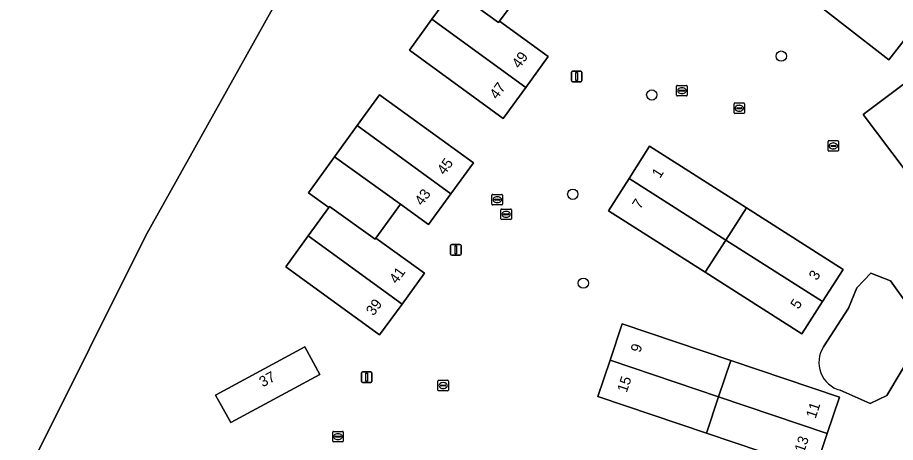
# Model space of a CAD drawing. Extents: x 159451 to 160664, y 388402 to 389723.
# Drawn here: x 159502.7 to 159586.1, y 389338.3 to 389378.7 of the extents above; entities that cross this region are included whole.
import ezdxf

# ---------------------------------------------------------------- set-up
doc = ezdxf.new("R2010")
doc.units = 0
for name, color, linetype in [('IMGEO_Boom', 7, 'Continuous'), ('IMGEO_Brandkraan', 7, 'Continuous'), ('IMGEO_Groenvoorziening', 7, 'Continuous'), ('IMGEO_Kolk', 7, 'Continuous'), ('IMGEO_Lichtmast', 7, 'Continuous'), ('IMGEO_Loofbos', 7, 'Continuous'), ('IMGEO_Meer_plas_ven_vijver', 7, 'Continuous'), ('IMGEO_Pand', 7, 'Continuous'), ('IMGEO_Pand_nummerreeks', 7, 'Continuous'), ('IMGEO_Rioolput', 7, 'Continuous')]:
    doc.layers.add(name, color=color, linetype=linetype)

msp = doc.modelspace()

# ---------------------------------------------------------------- linework, layer by layer
at = {"layer": 'IMGEO_Boom'}
for centre in [(159575.267, 389374.993), (159562.961, 389371.299), (159555.454, 389361.859), (159556.455, 389353.409)]:
    msp.add_circle(centre, 0.489, dxfattribs=at)
at = {"layer": 'IMGEO_Brandkraan'}
for p, q in [((159570.773, 389369.615), (159570.773, 389370.467)), ((159570.848, 389370.541), (159571.7, 389370.541)), ((159571.774, 389370.467), (159571.774, 389369.615)), ((159571.7, 389369.541), (159570.848, 389369.541)), ((159571.032, 389370.035), (159571.032, 389370.047)), ((159571.47, 389369.998), (159571.072, 389369.998)), ((159571.075, 389370.084), (159571.473, 389370.084)), ((159571.284, 389369.761), (159571.259, 389369.761)), ((159571.261, 389370.321), (159571.286, 389370.321)), ((159571.516, 389370.047), (159571.516, 389370.035))]:
    msp.add_line(p, q, dxfattribs=at)
for points in [[(159570.773, 389369.615), (159570.773, 389370.467)], [(159570.848, 389370.541), (159571.7, 389370.541)], [(159571.774, 389370.467), (159571.774, 389369.615)], [(159571.7, 389369.541), (159570.848, 389369.541)]]:
    msp.add_lwpolyline(points, dxfattribs=at)
for centre, radius, start, end in [((159570.85, 389370.465), 0.0765, 91.55205, 178.44795), ((159570.85, 389370.465), 0.0765, 91.55205, 178.44795), ((159571.698, 389370.465), 0.0765, 1.55205, 88.44795), ((159571.698, 389370.465), 0.0765, 1.55205, 88.44795), ((159570.85, 389369.617), 0.0765, 181.55205, 268.44795), ((159570.85, 389369.617), 0.0765, 181.55205, 268.44795), ((159571.072, 389370.044), 0.0403, 85.87752, 175.75265), ((159571.069, 389370.034), 0.0366, 178.93798, 274.71019), ((159571.473, 389370.041), 0.043, 264.86636, 352.45326), ((159571.477, 389370.046), 0.0386, 1.73085, 96.63898), ((159571.698, 389369.617), 0.0765, 271.55205, 358.44795), ((159571.698, 389369.617), 0.0765, 271.55205, 358.44795)]:
    msp.add_arc(centre, radius, start, end, dxfattribs=at)
for centre, major_axis, ratio, start_param, end_param in [((159571.26, 389370.041), (-0.387, 0.002), 0.722429, 4.712389, 7.853982), ((159571.285, 389370.041), (-0.39, 0.002), 0.717154, 1.570796, 4.712389)]:
    msp.add_ellipse(centre, major_axis=major_axis, ratio=ratio, start_param=start_param, end_param=end_param, dxfattribs=at)
at = {"layer": 'IMGEO_Groenvoorziening'}
for points in [[(159544.814, 389411.565), (159514.866, 389357.937), (159504.183, 389336.444), (159491.991, 389308.123), (159485.81, 389295.214), (159492.759, 389296.199), (159521.777, 389300.297)], [(159579.281, 389347.357), (159581.666, 389351.038), (159582.45, 389352.959), (159583.776, 389354.373), (159585.651, 389353.634), (159589.012, 389348.926)], [(159589.012, 389348.926), (159585.291, 389342.745), (159583.718, 389341.973), (159580.859, 389343.226)]]:
    msp.add_lwpolyline(points, dxfattribs=at)
for points in [[(159585.487, 389374.644), (159576.692, 389381.52), (159598.547, 389409.538), (159607.34, 389402.676)], [(159548.499, 389378.301), (159553.125, 389374.956), (159550.988, 389372.017), (159548.85, 389369.078), (159539.931, 389375.559), (159542.07, 389378.502), (159544.025, 389381.192), (159542.084, 389382.602), (159544.578, 389386.033), (159546.734, 389389), (159548.865, 389391.933), (159557.798, 389385.399), (159555.657, 389382.472), (159553.515, 389379.545), (159550.822, 389381.5)], [(159589.76, 389360.534), (159583.054, 389369.444), (159605.812, 389386.575), (159612.526, 389377.663)], [(159537.096, 389348.482), (159528.176, 389354.954), (159530.316, 389357.903), (159532.266, 389360.591), (159530.328, 389361.998), (159532.812, 389365.422), (159534.968, 389368.393), (159537.093, 389371.322), (159546.012, 389364.851), (159543.877, 389361.915), (159541.741, 389358.978), (159539.068, 389360.907), (159536.75, 389357.697), (159541.37, 389354.362), (159539.233, 389351.422)], [(159577.226, 389348.589), (159568.038, 389354.442), (159558.855, 389360.293), (159560.807, 389363.367), (159562.752, 389366.429), (159571.944, 389360.576), (159581.136, 389354.724), (159579.181, 389351.657)], [(159578.47, 389335.651), (159568.144, 389339.143), (159557.83, 389342.632), (159558.992, 389346.082), (159560.158, 389349.546), (159570.482, 389346.054), (159580.805, 389342.563), (159579.637, 389339.107)], [(159531.423, 389344.725), (159522.948, 389340.15), (159521.508, 389342.76), (159530.004, 389347.358)]]:
    msp.add_lwpolyline(points, close=True, dxfattribs=at)
msp.add_arc((159581.582, 389345.869), 2.74, 147.10719, 254.70551, dxfattribs=at)
at = {"layer": 'IMGEO_Kolk'}
for p, q in [((159565.323, 389371.283), (159565.323, 389372.135)), ((159565.398, 389372.209), (159566.25, 389372.209)), ((159566.324, 389372.135), (159566.324, 389371.283)), ((159566.25, 389371.209), (159565.398, 389371.209)), ((159565.582, 389371.703), (159565.582, 389371.715)), ((159566.02, 389371.666), (159565.622, 389371.666)), ((159565.625, 389371.752), (159566.023, 389371.752)), ((159565.834, 389371.429), (159565.809, 389371.429)), ((159565.811, 389371.989), (159565.836, 389371.989)), ((159566.066, 389371.715), (159566.066, 389371.703)), ((159542.632, 389343.252), (159542.632, 389344.104)), ((159542.707, 389344.178), (159543.559, 389344.178)), ((159542.891, 389343.672), (159542.891, 389343.684)), ((159542.934, 389343.721), (159543.332, 389343.721)), ((159543.12, 389343.958), (159543.145, 389343.958)), ((159543.375, 389343.684), (159543.375, 389343.672)), ((159543.633, 389344.104), (159543.633, 389343.252)), ((159543.559, 389343.178), (159542.707, 389343.178)), ((159543.329, 389343.635), (159542.931, 389343.635)), ((159543.143, 389343.398), (159543.118, 389343.398))]:
    msp.add_line(p, q, dxfattribs=at)
for points in [[(159565.323, 389371.283), (159565.323, 389372.135)], [(159565.398, 389372.209), (159566.25, 389372.209)], [(159566.324, 389372.135), (159566.324, 389371.283)], [(159566.25, 389371.209), (159565.398, 389371.209)], [(159542.632, 389343.252), (159542.632, 389344.104)], [(159542.707, 389344.178), (159543.559, 389344.178)], [(159543.633, 389344.104), (159543.633, 389343.252)], [(159543.559, 389343.178), (159542.707, 389343.178)]]:
    msp.add_lwpolyline(points, dxfattribs=at)
for centre, radius, start, end in [((159565.4, 389372.133), 0.0765, 91.55205, 178.44795), ((159565.4, 389372.133), 0.0765, 91.55205, 178.44795), ((159566.248, 389372.133), 0.0765, 1.55205, 88.44795), ((159566.248, 389372.133), 0.0765, 1.55205, 88.44795), ((159565.4, 389371.285), 0.0765, 181.55205, 268.44795), ((159565.4, 389371.285), 0.0765, 181.55205, 268.44795), ((159565.622, 389371.712), 0.0403, 85.87752, 175.75265), ((159565.619, 389371.702), 0.0366, 178.93798, 274.71019), ((159566.023, 389371.709), 0.043, 264.86636, 352.45326), ((159566.027, 389371.714), 0.0386, 1.73085, 96.63898), ((159566.248, 389371.285), 0.0765, 271.55205, 358.44795), ((159566.248, 389371.285), 0.0765, 271.55205, 358.44795), ((159542.709, 389344.102), 0.0765, 91.55205, 178.44795), ((159542.709, 389344.102), 0.0765, 91.55205, 178.44795), ((159542.931, 389343.681), 0.0403, 85.87752, 175.75265), ((159542.928, 389343.671), 0.0366, 178.93798, 274.71019), ((159543.332, 389343.678), 0.043, 264.86636, 352.45326), ((159543.336, 389343.683), 0.0386, 1.73085, 96.63898), ((159543.557, 389344.102), 0.0765, 1.55205, 88.44795), ((159543.557, 389344.102), 0.0765, 1.55205, 88.44795), ((159542.709, 389343.254), 0.0765, 181.55205, 268.44795), ((159542.709, 389343.254), 0.0765, 181.55205, 268.44795), ((159543.557, 389343.254), 0.0765, 271.55205, 358.44795), ((159543.557, 389343.254), 0.0765, 271.55205, 358.44795)]:
    msp.add_arc(centre, radius, start, end, dxfattribs=at)
for centre, major_axis, ratio, start_param, end_param in [((159565.81, 389371.709), (-0.387, 0.002), 0.722429, 4.712389, 7.853982), ((159565.835, 389371.709), (-0.39, 0.002), 0.717154, 1.570796, 4.712389), ((159543.119, 389343.678), (-0.387, 0.002), 0.722429, 4.712389, 7.853982), ((159543.144, 389343.678), (-0.39, 0.002), 0.717154, 1.570796, 4.712389)]:
    msp.add_ellipse(centre, major_axis=major_axis, ratio=ratio, start_param=start_param, end_param=end_param, dxfattribs=at)
at = {"layer": 'IMGEO_Lichtmast'}
for p, q in [((159555.326, 389372.663), (159555.326, 389373.463)), ((159555.326, 389373.463), (159555.326, 389372.663)), ((159555.426, 389373.563), (159556.216, 389373.563)), ((159556.216, 389373.563), (159555.426, 389373.563)), ((159556.316, 389373.463), (159556.316, 389372.663)), ((159556.316, 389372.663), (159556.316, 389373.463)), ((159556.216, 389372.563), (159555.426, 389372.563)), ((159555.426, 389372.563), (159556.216, 389372.563)), ((159543.945, 389357.081), (159544.735, 389357.081)), ((159544.735, 389357.081), (159543.945, 389357.081)), ((159543.845, 389356.181), (159543.845, 389356.981)), ((159543.845, 389356.981), (159543.845, 389356.181)), ((159544.835, 389356.981), (159544.835, 389356.181)), ((159544.835, 389356.181), (159544.835, 389356.981)), ((159544.735, 389356.081), (159543.945, 389356.081)), ((159543.945, 389356.081), (159544.735, 389356.081)), ((159535.364, 389344.07), (159535.364, 389344.87)), ((159535.364, 389344.87), (159535.364, 389344.07)), ((159535.464, 389344.97), (159536.254, 389344.97)), ((159536.254, 389344.97), (159535.464, 389344.97)), ((159536.354, 389344.87), (159536.354, 389344.07)), ((159536.354, 389344.07), (159536.354, 389344.87)), ((159536.254, 389343.97), (159535.464, 389343.97)), ((159535.464, 389343.97), (159536.254, 389343.97))]:
    msp.add_line(p, q, dxfattribs=at)
for points in [[(159555.746, 389373.438), (159555.896, 389373.438), (159555.896, 389372.688), (159555.746, 389372.688), (159555.746, 389373.438)], [(159544.265, 389356.956), (159544.415, 389356.956), (159544.415, 389356.206), (159544.265, 389356.206), (159544.265, 389356.956)], [(159535.784, 389344.845), (159535.934, 389344.845), (159535.934, 389344.095), (159535.784, 389344.095), (159535.784, 389344.845)]]:
    msp.add_lwpolyline(points, dxfattribs=at)
for centre, start, end in [((159555.426, 389373.463), 90, 180), ((159555.426, 389373.463), 90, 180), ((159556.216, 389373.463), 0, 90), ((159556.216, 389373.463), 360, 90), ((159555.426, 389372.663), 180, 270), ((159555.426, 389372.663), 180, 270), ((159556.216, 389372.663), 270, 0), ((159556.216, 389372.663), 270, 0), ((159543.945, 389356.981), 90, 180), ((159543.945, 389356.981), 90, 180), ((159544.735, 389356.981), 0, 90), ((159544.735, 389356.981), 360, 90), ((159543.945, 389356.181), 180, 270), ((159543.945, 389356.181), 180, 270), ((159544.735, 389356.181), 270, 0), ((159544.735, 389356.181), 270, 0), ((159535.464, 389344.87), 90, 180), ((159535.464, 389344.87), 90, 180), ((159536.254, 389344.87), 0, 90), ((159536.254, 389344.87), 360, 90), ((159535.464, 389344.07), 180, 270), ((159535.464, 389344.07), 180, 270), ((159536.254, 389344.07), 270, 0), ((159536.254, 389344.07), 270, 0)]:
    msp.add_arc(centre, 0.1, start, end, dxfattribs=at)
at = {"layer": 'IMGEO_Loofbos'}
msp.add_lwpolyline([(159475.093, 389317.376), (159476.799, 389293.936), (159485.81, 389295.214), (159491.991, 389308.123), (159504.183, 389336.444), (159514.866, 389357.937), (159544.814, 389411.565)], dxfattribs=at)
at = {"layer": 'IMGEO_Meer_plas_ven_vijver'}
for points in [[(159589.012, 389348.926), (159585.651, 389353.634), (159583.776, 389354.373), (159582.45, 389352.959), (159581.666, 389351.038), (159579.281, 389347.357)], [(159580.859, 389343.226), (159583.718, 389341.973), (159585.291, 389342.745), (159589.012, 389348.926)]]:
    msp.add_lwpolyline(points, dxfattribs=at)
msp.add_arc((159581.582, 389345.869), 2.74, 147.10719, 254.70551, dxfattribs=at)
at = {"layer": 'IMGEO_Pand'}
for points in [[(159607.34, 389402.676), (159598.547, 389409.538), (159576.692, 389381.52), (159585.487, 389374.644)], [(159612.526, 389377.663), (159605.812, 389386.575), (159583.054, 389369.444), (159589.76, 389360.534)], [(159544.578, 389386.033), (159542.084, 389382.602), (159544.025, 389381.192), (159544.107, 389381.305), (159548.409, 389378.178), (159548.499, 389378.301), (159550.822, 389381.5)], [(159548.499, 389378.301), (159548.409, 389378.178), (159544.107, 389381.305), (159544.025, 389381.192), (159542.07, 389378.502), (159550.988, 389372.017), (159553.125, 389374.956)], [(159542.07, 389378.502), (159539.931, 389375.559), (159548.85, 389369.078), (159550.988, 389372.017)], [(159537.093, 389371.322), (159534.968, 389368.393), (159543.877, 389361.915), (159546.012, 389364.851)], [(159534.968, 389368.393), (159532.812, 389365.422), (159539.068, 389360.907), (159541.741, 389358.978), (159543.877, 389361.915)], [(159562.752, 389366.429), (159560.807, 389363.367), (159569.993, 389357.512), (159571.944, 389360.576)], [(159532.812, 389365.422), (159530.328, 389361.998), (159532.266, 389360.591), (159532.344, 389360.698), (159536.664, 389357.578), (159536.75, 389357.697), (159539.068, 389360.907)], [(159560.807, 389363.367), (159558.855, 389360.293), (159568.038, 389354.442), (159569.993, 389357.512)], [(159536.75, 389357.697), (159536.664, 389357.578), (159532.344, 389360.698), (159532.266, 389360.591), (159530.316, 389357.903), (159539.233, 389351.422), (159541.37, 389354.362)], [(159571.944, 389360.576), (159569.993, 389357.512), (159579.181, 389351.657), (159581.136, 389354.724)], [(159530.316, 389357.903), (159528.176, 389354.954), (159537.096, 389348.482), (159539.233, 389351.422)], [(159569.993, 389357.512), (159568.038, 389354.442), (159577.226, 389348.589), (159579.181, 389351.657)], [(159560.158, 389349.546), (159558.992, 389346.082), (159569.312, 389342.595), (159570.482, 389346.054)], [(159531.423, 389344.725), (159530.004, 389347.358), (159521.508, 389342.76), (159522.948, 389340.15)], [(159558.992, 389346.082), (159557.83, 389342.632), (159568.144, 389339.143), (159569.312, 389342.595)], [(159570.482, 389346.054), (159569.312, 389342.595), (159579.637, 389339.107), (159580.805, 389342.563)], [(159569.312, 389342.595), (159568.144, 389339.143), (159578.47, 389335.651), (159579.637, 389339.107)]]:
    msp.add_lwpolyline(points, close=True, dxfattribs=at)
at = {"layer": 'IMGEO_Rioolput'}
for p, q in [((159579.707, 389366.033), (159579.707, 389366.885)), ((159579.782, 389366.959), (159580.634, 389366.959)), ((159579.966, 389366.453), (159579.966, 389366.465)), ((159580.404, 389366.416), (159580.006, 389366.416)), ((159580.009, 389366.502), (159580.407, 389366.502)), ((159580.218, 389366.179), (159580.193, 389366.179)), ((159580.195, 389366.739), (159580.22, 389366.739)), ((159580.45, 389366.465), (159580.45, 389366.453)), ((159580.708, 389366.885), (159580.708, 389366.033)), ((159580.634, 389365.959), (159579.782, 389365.959)), ((159547.775, 389360.92), (159547.775, 389361.772)), ((159547.85, 389361.846), (159548.702, 389361.846)), ((159548.034, 389361.34), (159548.034, 389361.352)), ((159548.472, 389361.303), (159548.074, 389361.303)), ((159548.077, 389361.389), (159548.475, 389361.389)), ((159548.263, 389361.626), (159548.288, 389361.626)), ((159548.518, 389361.352), (159548.518, 389361.34)), ((159548.776, 389361.772), (159548.776, 389360.92)), ((159548.702, 389360.846), (159547.85, 389360.846)), ((159548.286, 389361.066), (159548.261, 389361.066)), ((159548.621, 389359.532), (159548.621, 389360.384)), ((159548.696, 389360.458), (159549.548, 389360.458)), ((159549.622, 389360.384), (159549.622, 389359.532)), ((159548.88, 389359.952), (159548.88, 389359.964)), ((159549.318, 389359.915), (159548.92, 389359.915)), ((159548.923, 389360.001), (159549.321, 389360.001)), ((159549.132, 389359.678), (159549.107, 389359.678)), ((159549.109, 389360.238), (159549.134, 389360.238)), ((159549.364, 389359.964), (159549.364, 389359.952)), ((159549.548, 389359.458), (159548.696, 389359.458)), ((159532.639, 389338.395), (159532.639, 389339.247)), ((159532.714, 389339.321), (159533.566, 389339.321)), ((159532.898, 389338.815), (159532.898, 389338.827)), ((159533.336, 389338.778), (159532.938, 389338.778)), ((159532.941, 389338.864), (159533.339, 389338.864)), ((159533.127, 389339.101), (159533.152, 389339.101)), ((159533.382, 389338.827), (159533.382, 389338.815)), ((159533.64, 389339.247), (159533.64, 389338.395)), ((159533.566, 389338.321), (159532.714, 389338.321)), ((159533.15, 389338.541), (159533.125, 389338.541))]:
    msp.add_line(p, q, dxfattribs=at)
for points in [[(159579.707, 389366.033), (159579.707, 389366.885)], [(159579.782, 389366.959), (159580.634, 389366.959)], [(159580.708, 389366.885), (159580.708, 389366.033)], [(159580.634, 389365.959), (159579.782, 389365.959)], [(159547.775, 389360.92), (159547.775, 389361.772)], [(159547.85, 389361.846), (159548.702, 389361.846)], [(159548.776, 389361.772), (159548.776, 389360.92)], [(159548.702, 389360.846), (159547.85, 389360.846)], [(159548.621, 389359.532), (159548.621, 389360.384)], [(159548.696, 389360.458), (159549.548, 389360.458)], [(159549.622, 389360.384), (159549.622, 389359.532)], [(159549.548, 389359.458), (159548.696, 389359.458)], [(159532.639, 389338.395), (159532.639, 389339.247)], [(159532.714, 389339.321), (159533.566, 389339.321)], [(159533.64, 389339.247), (159533.64, 389338.395)], [(159533.566, 389338.321), (159532.714, 389338.321)]]:
    msp.add_lwpolyline(points, dxfattribs=at)
for centre, radius, start, end in [((159579.784, 389366.883), 0.0765, 91.55205, 178.44795), ((159579.784, 389366.883), 0.0765, 91.55205, 178.44795), ((159580.006, 389366.462), 0.0403, 85.87752, 175.75265), ((159580.003, 389366.452), 0.0366, 178.93798, 274.71019), ((159580.407, 389366.459), 0.043, 264.86636, 352.45326), ((159580.411, 389366.464), 0.0386, 1.73085, 96.63898), ((159580.632, 389366.883), 0.0765, 1.55205, 88.44795), ((159580.632, 389366.883), 0.0765, 1.55205, 88.44795), ((159579.784, 389366.035), 0.0765, 181.55205, 268.44795), ((159579.784, 389366.035), 0.0765, 181.55205, 268.44795), ((159580.632, 389366.035), 0.0765, 271.55205, 358.44795), ((159580.632, 389366.035), 0.0765, 271.55205, 358.44795), ((159547.852, 389361.77), 0.0765, 91.55205, 178.44795), ((159547.852, 389361.77), 0.0765, 91.55205, 178.44795), ((159548.074, 389361.349), 0.0403, 85.87752, 175.75265), ((159548.071, 389361.339), 0.0366, 178.93798, 274.71019), ((159548.475, 389361.346), 0.043, 264.86636, 352.45326), ((159548.479, 389361.351), 0.0386, 1.73085, 96.63898), ((159548.7, 389361.77), 0.0765, 1.55205, 88.44795), ((159548.7, 389361.77), 0.0765, 1.55205, 88.44795), ((159547.852, 389360.922), 0.0765, 181.55205, 268.44795), ((159547.852, 389360.922), 0.0765, 181.55205, 268.44795), ((159548.698, 389360.382), 0.0765, 91.55205, 178.44795), ((159548.698, 389360.382), 0.0765, 91.55205, 178.44795), ((159548.7, 389360.922), 0.0765, 271.55205, 358.44795), ((159548.7, 389360.922), 0.0765, 271.55205, 358.44795), ((159549.546, 389360.382), 0.0765, 1.55205, 88.44795), ((159549.546, 389360.382), 0.0765, 1.55205, 88.44795), ((159548.698, 389359.534), 0.0765, 181.55205, 268.44795), ((159548.698, 389359.534), 0.0765, 181.55205, 268.44795), ((159548.92, 389359.961), 0.0403, 85.87752, 175.75265), ((159548.917, 389359.951), 0.0366, 178.93798, 274.71019), ((159549.321, 389359.958), 0.043, 264.86636, 352.45326), ((159549.325, 389359.963), 0.0386, 1.73085, 96.63898), ((159549.546, 389359.534), 0.0765, 271.55205, 358.44795), ((159549.546, 389359.534), 0.0765, 271.55205, 358.44795), ((159532.716, 389339.245), 0.0765, 91.55205, 178.44795), ((159532.716, 389339.245), 0.0765, 91.55205, 178.44795), ((159532.938, 389338.824), 0.0403, 85.87752, 175.75265), ((159532.935, 389338.814), 0.0366, 178.93798, 274.71019), ((159533.339, 389338.821), 0.043, 264.86636, 352.45326), ((159533.343, 389338.826), 0.0386, 1.73085, 96.63898), ((159533.564, 389339.245), 0.0765, 1.55205, 88.44795), ((159533.564, 389339.245), 0.0765, 1.55205, 88.44795), ((159532.716, 389338.397), 0.0765, 181.55205, 268.44795), ((159532.716, 389338.397), 0.0765, 181.55205, 268.44795), ((159533.564, 389338.397), 0.0765, 271.55205, 358.44795), ((159533.564, 389338.397), 0.0765, 271.55205, 358.44795)]:
    msp.add_arc(centre, radius, start, end, dxfattribs=at)
for centre, major_axis, ratio, start_param, end_param in [((159580.194, 389366.459), (-0.387, 0.002), 0.722429, 4.712389, 7.853982), ((159580.219, 389366.459), (-0.39, 0.002), 0.717154, 1.570796, 4.712389), ((159548.262, 389361.346), (-0.387, 0.002), 0.722429, 4.712389, 7.853982), ((159548.287, 389361.346), (-0.39, 0.002), 0.717154, 1.570796, 4.712389), ((159549.108, 389359.958), (-0.387, 0.002), 0.722429, 4.712389, 7.853982), ((159549.133, 389359.958), (-0.39, 0.002), 0.717154, 1.570796, 4.712389), ((159533.126, 389338.821), (-0.387, 0.002), 0.722429, 4.712389, 7.853982), ((159533.151, 389338.821), (-0.39, 0.002), 0.717154, 1.570796, 4.712389)]:
    msp.add_ellipse(centre, major_axis=major_axis, ratio=ratio, start_param=start_param, end_param=end_param, dxfattribs=at)

# ---------------------------------------------------------------- texts
at = {"layer": 'IMGEO_Pand_nummerreeks'}
for s, rotation, p in [('49', 53.97262, (159550.385, 389373.739)), ('47', 53.97262, (159548.26, 389370.817)), ('45', 53.97262, (159543.266, 389363.625)), ('1', 57.58226, (159563.738, 389363.32)), ('43', 53.97262, (159541.139, 389360.701)), ('7', 57.58226, (159561.869, 389360.376)), ('41', 53.98981, (159538.725, 389353.273)), ('3', 57.49059, (159578.643, 389353.602)), ('39', 53.98981, (159536.52, 389350.24)), ('5', 57.49059, (159576.9, 389350.867)), ('9', 71.39054, (159561.851, 389346.743)), ('37', 28.36141, (159525.985, 389343.494)), ('15', 71.39054, (159560.574, 389342.946)), ('11', 71.33325, (159578.517, 389340.478)), ('13', 71.33325, (159577.429, 389337.254))]:
    msp.add_text(s, height=1, rotation=rotation, dxfattribs=at).set_placement(p)

doc.saveas('drawing.dxf')
